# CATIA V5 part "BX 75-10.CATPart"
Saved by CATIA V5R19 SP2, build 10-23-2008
Part number: BX 75-10
Bounding box of the stored display mesh (mm): x -15.868 to 15.868, y -15.868 to 15.868, z 0 to 75
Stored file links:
  C:\Users\Bora\Desktop\3D Katı model\BX serisi\BX 75\BX 75-10.CATPart
  C:\Program Files\Dassault Systemes\B19\intel_a\reffiles\standard\MetricThickPitch.txt
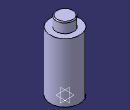
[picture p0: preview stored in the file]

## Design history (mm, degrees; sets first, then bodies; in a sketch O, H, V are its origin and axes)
Body1 (main body)
  Sketch1 on yz-plane, origin (0, 0, 0), H (0, 1, 0), V (0, 0, 1)
    line L1 (16, 64) -> (16, 0)
    point P4 (9.5, 74)
    line L2 (9.5, 74) -> (9.5, 64)
    point P6 (9.5, 74)
    arc A1 centre (8.5, 74) radius 1 from (9.5, 74) to (8.5, 75) ccw
    line L3 (8.5, 75) -> (0, 75)
    point P7 (0, 75)
    line L4 (9.5, 64) -> (16, 64)
    line L5 (0, 0) -> (16, 0)
    tangency: L3 A1
    coincidence: P7 V, P4 P6
    horizontal: L4 H, L5 H
  Shaft1: profile Sketch1, axis Sketch1.V, angle 360
  Sketch2 on face of Shaft1 from Sketch1.L5, origin (0, 0, 0), H (1, 0, 0), V (0, -1, 0)
    point P1 (7.5, 0)
    distance P1 V = 7.5
  Hole1: placed by Sketch2, at (7.5, 0, 0) direction (0, 0, 1), diameter 3.242, depth 5, threaded "M4", thread diameter 4, thread depth 5, pitch 0.7
  Sketch3 on face of Shaft1 from Sketch1.L5, origin (0, 0, 0), H (1, 0, 0), V (0, -1, 0)
    point P1 (-7.5, 0)
    distance V P1 = 7.5
  Hole2: placed by Sketch3, at (-7.5, 0, 0) direction (0, 0, 1), diameter 3.242, depth 5, threaded "M4", thread diameter 4, thread depth 5, pitch 0.7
